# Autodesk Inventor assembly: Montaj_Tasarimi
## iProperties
Shininess: 64.0
Length Units: 11269
Angle Units: 11279
Time Units: 11290
Mass Units: 11286
Length Display Precision: 3
Angle Display Precision: 2
Compacted: True
Part Number: Montaj_Tasarimi
Document SubType Name: Assembly
Created: 2003-06
Designer: Administrator
Manufacturer: Standard
Standards Organization: Custom
Density: 0.0
Volumn: 0.0
Area: 0.0
PropertySet Name: Model Information
Control State: 0
Master: False
Checked Out: False
Author: Administrator
